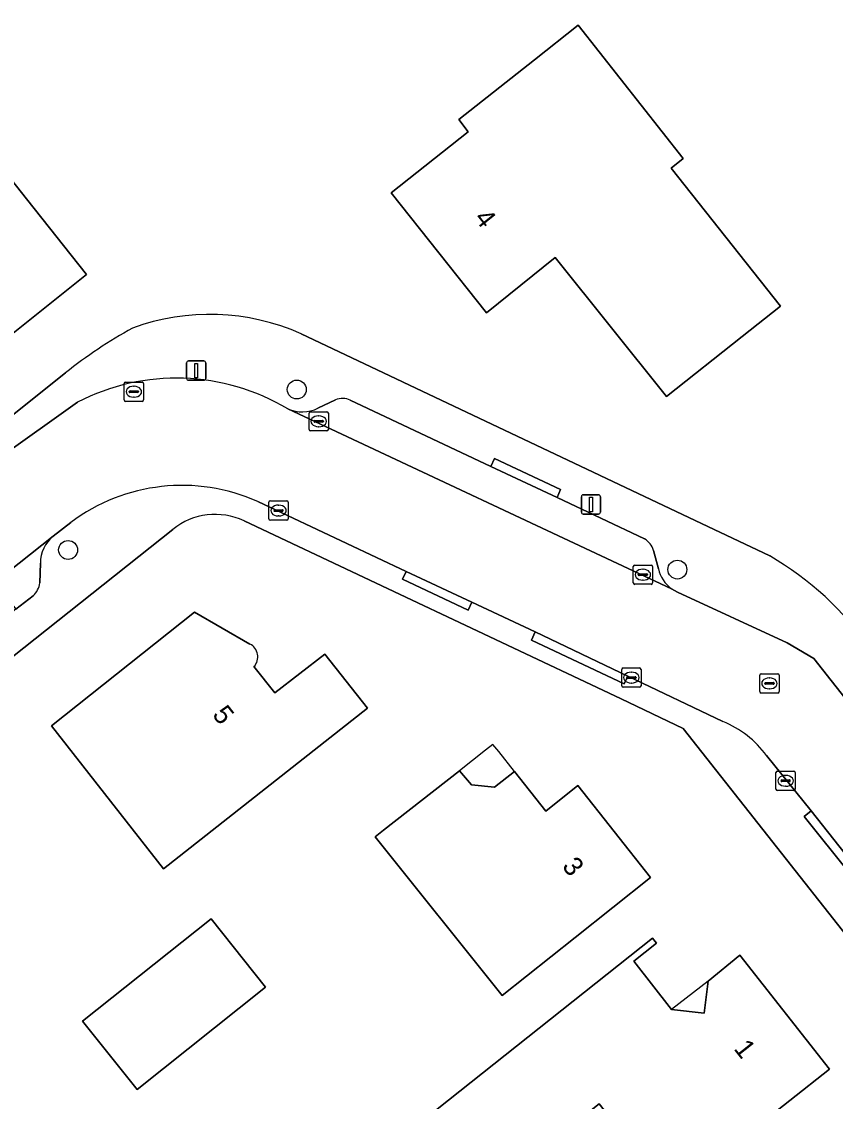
# Model space of a CAD drawing. Extents: x 159626 to 160723, y 388173 to 389416.
# Drawn here: x 159947.2 to 159989.4, y 388604.8 to 388660.7 of the extents above; entities that cross this region are included whole.
import ezdxf

# ---------------------------------------------------------------- set-up
doc = ezdxf.new("R2010")
doc.units = 0
for name, color, linetype in [('IMGEO_Boom', 7, 'Continuous'), ('IMGEO_Erf', 7, 'Continuous'), ('IMGEO_Kolk', 7, 'Continuous'), ('IMGEO_Lichtmast', 7, 'Continuous'), ('IMGEO_Pand', 7, 'Continuous'), ('IMGEO_Pand_nummerreeks', 7, 'Continuous'), ('IMGEO_Pand_overbouw', 7, 'Continuous'), ('IMGEO_Parkeervlak_open', 7, 'Continuous'), ('IMGEO_Rijbaan_lokaal_open', 7, 'Continuous'), ('IMGEO_Rioolput', 7, 'Continuous'), ('IMGEO_Voetpad_open', 7, 'Continuous')]:
    doc.layers.add(name, color=color, linetype=linetype)

msp = doc.modelspace()

# ---------------------------------------------------------------- linework, layer by layer
at = {"layer": 'IMGEO_Boom'}
for centre in [(159961.483, 388641.658), (159949.629, 388633.346), (159981.213, 388632.329)]:
    msp.add_circle(centre, 0.489, dxfattribs=at)
at = {"layer": 'IMGEO_Erf'}
for points in [[(159944.685, 388642.929), (159944.5, 388641.838), (159942.579, 388640.32), (159941.469, 388640.402), (159941.101, 388640.109), (159936.4, 388646.038), (159938.761, 388647.945), (159939.373, 388648.442), (159938.292, 388649.91), (159937.645, 388649.313), (159933.084, 388655.085), (159937.002, 388658.193), (159940.192, 388660.724), (159947.475, 388651.543), (159950.583, 388647.626)], [(159981.523, 388653.629), (159980.897, 388653.134), (159986.558, 388645.973), (159984.577, 388644.407), (159980.655, 388641.305), (159974.884, 388648.501), (159971.32, 388645.631), (159966.37, 388651.85), (159970.377, 388655.018), (159969.882, 388655.644), (159973.805, 388658.745), (159976.066, 388660.532)], [(159965.554, 388618.482), (159965.985, 388618.82), (159969.918, 388621.906), (159970.55, 388621.181), (159971.742, 388621.064), (159972.765, 388621.862), (159974.401, 388619.82), (159976.062, 388621.142), (159979.827, 388616.37), (159975.909, 388613.265), (159972.123, 388610.264)], [(159950.38, 388608.93), (159957.042, 388614.232), (159959.861, 388610.685), (159953.201, 388605.385)], [(159977.152, 388604.649), (159974.803, 388602.785), (159974.431, 388603.254), (159971.308, 388600.776), (159969.731, 388599.525), (159966.996, 388602.972), (159971.696, 388606.701), (159979.927, 388613.231), (159980.13, 388612.965), (159978.952, 388612.041), (159980.918, 388609.537), (159982.606, 388609.353), (159982.809, 388611.002), (159984.451, 388612.35), (159989.108, 388606.451), (159980.88, 388599.95)]]:
    msp.add_lwpolyline(points, close=True, dxfattribs=at)
for points in [[(159961.709, 388644.549), (159982.465, 388634.72), (159986.01, 388633.035)], [(159939.758, 388634.891), (159940.172, 388635.094), (159949.489, 388642.527)], [(159994.869, 388607.162), (159981.506, 388624.102), (159978.304, 388625.626), (159958.752, 388634.855)], [(159955.063, 388634.415), (159911.466, 388599.82)], [(159948.766, 388624.226), (159956.185, 388630.121), (159959.052, 388628.472)], [(159959.266, 388627.3), (159960.348, 388625.938), (159962.942, 388627.943), (159965.142, 388625.158), (159954.57, 388616.83), (159948.766, 388624.226)]]:
    msp.add_lwpolyline(points, dxfattribs=at)
for centre, radius, start, end in [((159956.977, 388633.896), 11.656, 66.0505, 110.1089), ((159965.53, 388622.181), 25.909, 118.9981, 128.2528), ((159957.259, 388631.684), 3.505, 64.7934, 128.8101), ((159977.913, 388619.061), 16.15, 34.6568, 59.9116), ((159958.727, 388627.807), 0.74, 316.7507, 63.945)]:
    msp.add_arc(centre, radius, start, end, dxfattribs=at)
at = {"layer": 'IMGEO_Kolk'}
for p, q in [((159962.194, 388640.512), (159963.046, 388640.512)), ((159962.119, 388639.586), (159962.119, 388640.438)), ((159962.378, 388640.006), (159962.378, 388640.018)), ((159962.816, 388639.969), (159962.418, 388639.969)), ((159962.421, 388640.055), (159962.819, 388640.055)), ((159962.607, 388640.292), (159962.632, 388640.292)), ((159962.862, 388640.018), (159962.862, 388640.006)), ((159963.12, 388640.438), (159963.12, 388639.586)), ((159963.046, 388639.512), (159962.194, 388639.512)), ((159962.63, 388639.732), (159962.605, 388639.732)), ((159960.038, 388634.963), (159960.038, 388635.815)), ((159960.113, 388635.889), (159960.965, 388635.889)), ((159960.34, 388635.432), (159960.738, 388635.432)), ((159960.526, 388635.669), (159960.551, 388635.669)), ((159961.039, 388635.815), (159961.039, 388634.963)), ((159960.965, 388634.889), (159960.113, 388634.889)), ((159960.297, 388635.383), (159960.297, 388635.395)), ((159960.735, 388635.346), (159960.337, 388635.346)), ((159960.549, 388635.109), (159960.524, 388635.109)), ((159960.781, 388635.395), (159960.781, 388635.383)), ((159978.927, 388631.64), (159978.927, 388632.492)), ((159979.002, 388632.566), (159979.854, 388632.566)), ((159979.186, 388632.06), (159979.186, 388632.072)), ((159979.229, 388632.109), (159979.627, 388632.109)), ((159979.415, 388632.346), (159979.44, 388632.346)), ((159979.67, 388632.072), (159979.67, 388632.06)), ((159979.928, 388632.492), (159979.928, 388631.64)), ((159979.854, 388631.566), (159979.002, 388631.566)), ((159979.624, 388632.023), (159979.226, 388632.023)), ((159979.438, 388631.786), (159979.413, 388631.786)), ((159978.329, 388626.307), (159978.329, 388627.159)), ((159978.404, 388627.233), (159979.256, 388627.233)), ((159979.33, 388627.159), (159979.33, 388626.307)), ((159978.588, 388626.727), (159978.588, 388626.739)), ((159979.026, 388626.69), (159978.628, 388626.69)), ((159978.631, 388626.776), (159979.029, 388626.776)), ((159978.817, 388627.013), (159978.842, 388627.013)), ((159979.072, 388626.739), (159979.072, 388626.727)), ((159979.256, 388626.233), (159978.404, 388626.233)), ((159978.84, 388626.453), (159978.815, 388626.453)), ((159986.326, 388620.96), (159986.326, 388621.812)), ((159986.401, 388621.886), (159987.253, 388621.886)), ((159986.628, 388621.429), (159987.026, 388621.429)), ((159986.814, 388621.666), (159986.839, 388621.666)), ((159987.327, 388621.812), (159987.327, 388620.96)), ((159987.253, 388620.886), (159986.401, 388620.886)), ((159986.585, 388621.38), (159986.585, 388621.392)), ((159987.023, 388621.343), (159986.625, 388621.343)), ((159986.837, 388621.106), (159986.812, 388621.106)), ((159987.069, 388621.392), (159987.069, 388621.38))]:
    msp.add_line(p, q, dxfattribs=at)
for points in [[(159962.194, 388640.512), (159963.046, 388640.512)], [(159962.119, 388639.586), (159962.119, 388640.438)], [(159963.12, 388640.438), (159963.12, 388639.586)], [(159963.046, 388639.512), (159962.194, 388639.512)], [(159960.038, 388634.963), (159960.038, 388635.815)], [(159960.113, 388635.889), (159960.965, 388635.889)], [(159961.039, 388635.815), (159961.039, 388634.963)], [(159960.965, 388634.889), (159960.113, 388634.889)], [(159978.927, 388631.64), (159978.927, 388632.492)], [(159979.002, 388632.566), (159979.854, 388632.566)], [(159979.928, 388632.492), (159979.928, 388631.64)], [(159979.854, 388631.566), (159979.002, 388631.566)], [(159978.329, 388626.307), (159978.329, 388627.159)], [(159978.404, 388627.233), (159979.256, 388627.233)], [(159979.33, 388627.159), (159979.33, 388626.307)], [(159979.256, 388626.233), (159978.404, 388626.233)], [(159986.326, 388620.96), (159986.326, 388621.812)], [(159986.401, 388621.886), (159987.253, 388621.886)], [(159987.327, 388621.812), (159987.327, 388620.96)], [(159987.253, 388620.886), (159986.401, 388620.886)]]:
    msp.add_lwpolyline(points, dxfattribs=at)
for centre, radius, start, end in [((159962.196, 388640.436), 0.0765, 91.552, 178.448), ((159962.196, 388640.436), 0.0765, 91.552, 178.448), ((159963.044, 388640.436), 0.0765, 1.552, 88.448), ((159963.044, 388640.436), 0.0765, 1.552, 88.448), ((159962.418, 388640.015), 0.0403, 85.8775, 175.7526), ((159962.415, 388640.005), 0.0366, 178.938, 274.7102), ((159962.819, 388640.012), 0.043, 264.8664, 352.4533), ((159962.823, 388640.017), 0.0386, 1.7309, 96.639), ((159962.196, 388639.588), 0.0765, 181.552, 268.448), ((159962.196, 388639.588), 0.0765, 181.552, 268.448), ((159963.044, 388639.588), 0.0765, 271.552, 358.448), ((159963.044, 388639.588), 0.0765, 271.552, 358.448), ((159960.115, 388635.813), 0.0765, 91.552, 178.448), ((159960.115, 388635.813), 0.0765, 91.552, 178.448), ((159960.337, 388635.392), 0.0403, 85.8775, 175.7526), ((159960.742, 388635.394), 0.0386, 1.7309, 96.639), ((159960.963, 388635.813), 0.0765, 1.552, 88.448), ((159960.963, 388635.813), 0.0765, 1.552, 88.448), ((159960.115, 388634.965), 0.0765, 181.552, 268.448), ((159960.115, 388634.965), 0.0765, 181.552, 268.448), ((159960.334, 388635.382), 0.0366, 178.938, 274.7102), ((159960.738, 388635.389), 0.043, 264.8664, 352.4533), ((159960.963, 388634.965), 0.0765, 271.552, 358.448), ((159960.963, 388634.965), 0.0765, 271.552, 358.448), ((159979.004, 388632.49), 0.0765, 91.552, 178.448), ((159979.004, 388632.49), 0.0765, 91.552, 178.448), ((159979.226, 388632.069), 0.0403, 85.8775, 175.7526), ((159979.223, 388632.059), 0.0366, 178.938, 274.7102), ((159979.627, 388632.066), 0.043, 264.8664, 352.4533), ((159979.631, 388632.071), 0.0386, 1.7309, 96.639), ((159979.852, 388632.49), 0.0765, 1.552, 88.448), ((159979.852, 388632.49), 0.0765, 1.552, 88.448), ((159979.004, 388631.642), 0.0765, 181.552, 268.448), ((159979.004, 388631.642), 0.0765, 181.552, 268.448), ((159979.852, 388631.642), 0.0765, 271.552, 358.448), ((159979.852, 388631.642), 0.0765, 271.552, 358.448), ((159978.406, 388627.157), 0.0765, 91.552, 178.448), ((159978.406, 388627.157), 0.0765, 91.552, 178.448), ((159979.254, 388627.157), 0.0765, 1.552, 88.448), ((159979.254, 388627.157), 0.0765, 1.552, 88.448), ((159978.628, 388626.736), 0.0403, 85.8775, 175.7526), ((159978.625, 388626.726), 0.0366, 178.938, 274.7102), ((159979.029, 388626.733), 0.043, 264.8664, 352.4533), ((159979.033, 388626.738), 0.0386, 1.7309, 96.639), ((159978.406, 388626.309), 0.0765, 181.552, 268.448), ((159978.406, 388626.309), 0.0765, 181.552, 268.448), ((159979.254, 388626.309), 0.0765, 271.552, 358.448), ((159979.254, 388626.309), 0.0765, 271.552, 358.448), ((159986.403, 388621.81), 0.0765, 91.552, 178.448), ((159986.403, 388621.81), 0.0765, 91.552, 178.448), ((159986.625, 388621.389), 0.0403, 85.8775, 175.7526), ((159987.03, 388621.391), 0.0386, 1.7309, 96.639), ((159987.251, 388621.81), 0.0765, 1.552, 88.448), ((159987.251, 388621.81), 0.0765, 1.552, 88.448), ((159986.403, 388620.962), 0.0765, 181.552, 268.448), ((159986.403, 388620.962), 0.0765, 181.552, 268.448), ((159986.622, 388621.379), 0.0366, 178.938, 274.7102), ((159987.026, 388621.386), 0.043, 264.8664, 352.4533), ((159987.251, 388620.962), 0.0765, 271.552, 358.448), ((159987.251, 388620.962), 0.0765, 271.552, 358.448)]:
    msp.add_arc(centre, radius, start, end, dxfattribs=at)
for centre, major_axis, ratio, start_param, end_param in [((159962.606, 388640.012), (-0.387, 0.002), 0.722429, 4.712389, 7.853982), ((159962.631, 388640.012), (-0.39, 0.002), 0.717154, 1.570796, 4.712389), ((159960.525, 388635.389), (-0.387, 0.002), 0.722429, 4.712389, 7.853982), ((159960.55, 388635.389), (-0.39, 0.002), 0.717154, 1.570796, 4.712389), ((159979.414, 388632.066), (-0.387, 0.002), 0.722429, 4.712389, 7.853982), ((159979.439, 388632.066), (-0.39, 0.002), 0.717154, 1.570796, 4.712389), ((159978.816, 388626.733), (-0.387, 0.002), 0.722429, 4.712389, 7.853982), ((159978.841, 388626.733), (-0.39, 0.002), 0.717154, 1.570796, 4.712389), ((159986.813, 388621.386), (-0.387, 0.002), 0.722429, 4.712389, 7.853982), ((159986.838, 388621.386), (-0.39, 0.002), 0.717154, 1.570796, 4.712389)]:
    msp.add_ellipse(centre, major_axis=major_axis, ratio=ratio, start_param=start_param, end_param=end_param, dxfattribs=at)
at = {"layer": 'IMGEO_Lichtmast'}
for p, q in [((159955.774, 388642.238), (159955.774, 388643.038)), ((159955.774, 388643.038), (159955.774, 388642.238)), ((159955.874, 388643.138), (159956.664, 388643.138)), ((159956.664, 388643.138), (159955.874, 388643.138)), ((159956.764, 388643.038), (159956.764, 388642.238)), ((159956.764, 388642.238), (159956.764, 388643.038)), ((159956.664, 388642.138), (159955.874, 388642.138)), ((159955.874, 388642.138), (159956.664, 388642.138)), ((159976.236, 388635.305), (159976.236, 388636.105)), ((159976.236, 388636.105), (159976.236, 388635.305)), ((159976.336, 388636.205), (159977.126, 388636.205)), ((159977.126, 388636.205), (159976.336, 388636.205)), ((159977.226, 388636.105), (159977.226, 388635.305)), ((159977.226, 388635.305), (159977.226, 388636.105)), ((159977.126, 388635.205), (159976.336, 388635.205)), ((159976.336, 388635.205), (159977.126, 388635.205))]:
    msp.add_line(p, q, dxfattribs=at)
for points in [[(159956.194, 388643.013), (159956.344, 388643.013), (159956.344, 388642.263), (159956.194, 388642.263), (159956.194, 388643.013)], [(159976.656, 388636.08), (159976.806, 388636.08), (159976.806, 388635.33), (159976.656, 388635.33), (159976.656, 388636.08)]]:
    msp.add_lwpolyline(points, dxfattribs=at)
for centre, start, end in [((159955.874, 388643.038), 90, 180), ((159955.874, 388643.038), 90, 180), ((159956.664, 388643.038), 0, 90), ((159956.664, 388643.038), 360, 90), ((159955.874, 388642.238), 180, 270), ((159955.874, 388642.238), 180, 270), ((159956.664, 388642.238), 270, 0), ((159956.664, 388642.238), 270, 0), ((159976.336, 388636.105), 90, 180), ((159976.336, 388636.105), 90, 180), ((159977.126, 388636.105), 0, 90), ((159977.126, 388636.105), 360, 90), ((159976.336, 388635.305), 180, 270), ((159976.336, 388635.305), 180, 270), ((159977.126, 388635.305), 270, 0), ((159977.126, 388635.305), 270, 0)]:
    msp.add_arc(centre, 0.1, start, end, dxfattribs=at)
at = {"layer": 'IMGEO_Pand'}
for points in [[(159937.645, 388649.313), (159938.292, 388649.91), (159939.373, 388648.442), (159938.761, 388647.945), (159936.4, 388646.038), (159941.101, 388640.109), (159941.469, 388640.402), (159942.579, 388640.32), (159944.5, 388641.838), (159944.685, 388642.929), (159950.583, 388647.626), (159947.475, 388651.543), (159940.192, 388660.724), (159937.002, 388658.193), (159933.084, 388655.085)], [(159984.577, 388644.407), (159986.558, 388645.973), (159980.897, 388653.134), (159981.523, 388653.629), (159976.066, 388660.532), (159973.805, 388658.745), (159969.882, 388655.644), (159970.377, 388655.018), (159966.37, 388651.85), (159971.32, 388645.631), (159974.884, 388648.501), (159980.655, 388641.305)], [(159969.918, 388621.906), (159965.985, 388618.82), (159965.554, 388618.482), (159972.123, 388610.264), (159975.909, 388613.265), (159979.827, 388616.37), (159976.062, 388621.142), (159974.401, 388619.82), (159972.765, 388621.862), (159971.742, 388621.064), (159970.55, 388621.181)], [(159953.201, 388605.385), (159959.861, 388610.685), (159957.042, 388614.232), (159950.38, 388608.93)], [(159989.108, 388606.451), (159984.451, 388612.35), (159982.809, 388611.002), (159982.606, 388609.353), (159980.918, 388609.537), (159978.952, 388612.041), (159980.13, 388612.965), (159979.927, 388613.231), (159971.696, 388606.701), (159966.996, 388602.972), (159969.731, 388599.525), (159971.308, 388600.776), (159974.431, 388603.254), (159974.803, 388602.785), (159977.152, 388604.649), (159980.88, 388599.95)]]:
    msp.add_lwpolyline(points, close=True, dxfattribs=at)
msp.add_lwpolyline([(159959.052, 388628.472), (159956.185, 388630.121), (159948.766, 388624.226), (159954.57, 388616.83), (159965.142, 388625.158), (159962.942, 388627.943), (159960.348, 388625.938), (159959.266, 388627.3)], dxfattribs=at)
msp.add_arc((159958.727, 388627.807), 0.74, 316.7507, 63.945, dxfattribs=at)
at = {"layer": 'IMGEO_Pand_overbouw'}
for points in [[(159969.918, 388621.906), (159970.55, 388621.181), (159971.742, 388621.064), (159972.765, 388621.862), (159971.959, 388622.898), (159971.655, 388623.275), (159971.271, 388622.975)], [(159982.809, 388611.002), (159980.918, 388609.537), (159982.606, 388609.353)]]:
    msp.add_lwpolyline(points, close=True, dxfattribs=at)
at = {"layer": 'IMGEO_Parkeervlak_open'}
for points in [[(159963.493, 388641.127), (159962.582, 388640.687)], [(159979.509, 388633.923), (159974.977, 388636.06), (159971.546, 388637.677), (159964.258, 388641.113)], [(159961.021, 388640.652), (159980.906, 388631.34)], [(159948.847, 388634.062), (159946.507, 388632.202), (159945.827, 388631.669), (159946.926, 388630.28), (159947.812, 388630.975)], [(159980.232, 388632.374), (159979.983, 388633.323)], [(159948.164, 388631.645), (159948.193, 388632.661)]]:
    msp.add_lwpolyline(points, dxfattribs=at)
for centre, radius, start, end in [((159963.859, 388640.246), 0.955, 65.3251, 112.578), ((159961.763, 388642.371), 1.872, 246.6401, 295.9288), ((159950.025, 388632.659), 1.832, 130.0141, 179.9387), ((159978.969, 388633.009), 1.062, 17.2048, 59.4127), ((159981.946, 388632.754), 1.755, 192.5149, 233.6807), ((159947.098, 388631.777), 1.074, 311.6505, 352.9171)]:
    msp.add_arc(centre, radius, start, end, dxfattribs=at)
at = {"layer": 'IMGEO_Rijbaan_lokaal_open'}
for points in [[(159950.122, 388641.005), (159946.049, 388638.119), (159943.49, 388636.12), (159942.807, 388635.575), (159945.827, 388631.669), (159946.507, 388632.202), (159948.847, 388634.062), (159949.767, 388634.774)], [(159985.833, 388622.694), (159988.152, 388619.823), (159990.497, 388616.852), (159994.461, 388611.83), (159998.383, 388614.922), (159988.285, 388627.721), (159986.905, 388628.53), (159981.225, 388631.153), (159980.906, 388631.34), (159961.021, 388640.652)], [(159959.462, 388635.859), (159967.155, 388632.23), (159970.561, 388630.635), (159973.844, 388629.101), (159978.653, 388626.808), (159983.578, 388624.453)]]:
    msp.add_lwpolyline(points, dxfattribs=at)
for centre, radius, start, end in [((159955.255, 388631.046), 11.204, 59.0237, 117.2662), ((159955.54, 388627.05), 9.642, 65.997, 126.7742), ((159981.682, 388619.697), 5.12, 35.8263, 68.2621)]:
    msp.add_arc(centre, radius, start, end, dxfattribs=at)
at = {"layer": 'IMGEO_Rioolput'}
for p, q in [((159952.537, 388641.122), (159952.537, 388641.974)), ((159952.612, 388642.048), (159953.464, 388642.048)), ((159952.839, 388641.591), (159953.237, 388641.591)), ((159953.025, 388641.828), (159953.05, 388641.828)), ((159953.538, 388641.974), (159953.538, 388641.122)), ((159953.464, 388641.048), (159952.612, 388641.048)), ((159952.796, 388641.542), (159952.796, 388641.554)), ((159953.234, 388641.505), (159952.836, 388641.505)), ((159953.048, 388641.268), (159953.023, 388641.268)), ((159953.28, 388641.554), (159953.28, 388641.542)), ((159985.487, 388626.008), (159985.487, 388626.86)), ((159985.562, 388626.934), (159986.414, 388626.934)), ((159985.789, 388626.477), (159986.187, 388626.477)), ((159985.975, 388626.714), (159986, 388626.714)), ((159986.488, 388626.86), (159986.488, 388626.008)), ((159986.414, 388625.934), (159985.562, 388625.934)), ((159985.746, 388626.428), (159985.746, 388626.44)), ((159986.184, 388626.391), (159985.786, 388626.391)), ((159985.998, 388626.154), (159985.973, 388626.154)), ((159986.23, 388626.44), (159986.23, 388626.428))]:
    msp.add_line(p, q, dxfattribs=at)
for points in [[(159952.537, 388641.122), (159952.537, 388641.974)], [(159952.612, 388642.048), (159953.464, 388642.048)], [(159953.538, 388641.974), (159953.538, 388641.122)], [(159953.464, 388641.048), (159952.612, 388641.048)], [(159985.487, 388626.008), (159985.487, 388626.86)], [(159985.562, 388626.934), (159986.414, 388626.934)], [(159986.488, 388626.86), (159986.488, 388626.008)], [(159986.414, 388625.934), (159985.562, 388625.934)]]:
    msp.add_lwpolyline(points, dxfattribs=at)
for centre, radius, start, end in [((159952.614, 388641.972), 0.0765, 91.552, 178.448), ((159952.614, 388641.972), 0.0765, 91.552, 178.448), ((159952.836, 388641.551), 0.0403, 85.8775, 175.7526), ((159953.241, 388641.553), 0.0386, 1.7309, 96.639), ((159953.462, 388641.972), 0.0765, 1.552, 88.448), ((159953.462, 388641.972), 0.0765, 1.552, 88.448), ((159952.614, 388641.124), 0.0765, 181.552, 268.448), ((159952.614, 388641.124), 0.0765, 181.552, 268.448), ((159952.833, 388641.541), 0.0366, 178.938, 274.7102), ((159953.237, 388641.548), 0.043, 264.8664, 352.4533), ((159953.462, 388641.124), 0.0765, 271.552, 358.448), ((159953.462, 388641.124), 0.0765, 271.552, 358.448), ((159985.564, 388626.858), 0.0765, 91.552, 178.448), ((159985.564, 388626.858), 0.0765, 91.552, 178.448), ((159985.786, 388626.437), 0.0403, 85.8775, 175.7526), ((159986.191, 388626.439), 0.0386, 1.7309, 96.639), ((159986.412, 388626.858), 0.0765, 1.552, 88.448), ((159986.412, 388626.858), 0.0765, 1.552, 88.448), ((159985.564, 388626.01), 0.0765, 181.552, 268.448), ((159985.564, 388626.01), 0.0765, 181.552, 268.448), ((159985.783, 388626.427), 0.0366, 178.938, 274.7102), ((159986.187, 388626.434), 0.043, 264.8664, 352.4533), ((159986.412, 388626.01), 0.0765, 271.552, 358.448), ((159986.412, 388626.01), 0.0765, 271.552, 358.448)]:
    msp.add_arc(centre, radius, start, end, dxfattribs=at)
for centre, major_axis, ratio, start_param, end_param in [((159953.024, 388641.548), (-0.387, 0.002), 0.722429, 4.712389, 7.853982), ((159953.049, 388641.548), (-0.39, 0.002), 0.717154, 1.570796, 4.712389), ((159985.974, 388626.434), (-0.387, 0.002), 0.722429, 4.712389, 7.853982), ((159985.999, 388626.434), (-0.39, 0.002), 0.717154, 1.570796, 4.712389)]:
    msp.add_ellipse(centre, major_axis=major_axis, ratio=ratio, start_param=start_param, end_param=end_param, dxfattribs=at)
at = {"layer": 'IMGEO_Voetpad_open'}
for points in [[(159986.01, 388633.035), (159982.465, 388634.72), (159961.709, 388644.549)], [(159949.489, 388642.527), (159940.172, 388635.094), (159937.609, 388633.116)], [(159962.582, 388640.687), (159963.493, 388641.127)], [(159964.258, 388641.113), (159971.546, 388637.677), (159971.739, 388638.078), (159975.157, 388636.481), (159974.977, 388636.06), (159979.509, 388633.923)], [(159940.194, 388633.536), (159942.807, 388635.575), (159943.49, 388636.12), (159946.049, 388638.119), (159950.122, 388641.005)], [(159983.578, 388624.453), (159978.653, 388626.808), (159978.45, 388626.414), (159973.656, 388628.679), (159973.844, 388629.101), (159970.561, 388630.635), (159970.367, 388630.223), (159966.964, 388631.825), (159967.155, 388632.23), (159959.462, 388635.859)], [(159958.752, 388634.855), (159978.304, 388625.626), (159981.506, 388624.102), (159994.869, 388607.162), (159996.498, 388609.249), (159996.163, 388609.674), (159994.461, 388611.83), (159990.497, 388616.852), (159990.147, 388616.581), (159987.791, 388619.541), (159988.152, 388619.823), (159985.833, 388622.694)], [(159911.466, 388599.82), (159955.063, 388634.415)], [(159949.767, 388634.774), (159948.847, 388634.062)], [(159979.983, 388633.323), (159980.232, 388632.374)], [(159948.193, 388632.661), (159948.164, 388631.645)], [(159947.812, 388630.975), (159946.926, 388630.28), (159935.008, 388620.788), (159935.318, 388620.396), (159929.383, 388615.697), (159929.073, 388616.089), (159917.343, 388606.776)], [(159980.906, 388631.34), (159981.225, 388631.153), (159986.905, 388628.53), (159988.285, 388627.721), (159998.383, 388614.922), (160000.014, 388612.793), (160000.751, 388611.921), (160002.97, 388613.298), (160000, 388617.069)]]:
    msp.add_lwpolyline(points, dxfattribs=at)
for points in [[(159971.546, 388637.677), (159974.977, 388636.06), (159975.157, 388636.481), (159971.739, 388638.078)], [(159967.155, 388632.23), (159966.964, 388631.825), (159970.367, 388630.223), (159970.561, 388630.635)], [(159978.653, 388626.808), (159973.844, 388629.101), (159973.656, 388628.679), (159978.45, 388626.414)], [(159988.152, 388619.823), (159987.791, 388619.541), (159990.147, 388616.581), (159990.497, 388616.852)]]:
    msp.add_lwpolyline(points, close=True, dxfattribs=at)
for centre, radius, start, end in [((159956.977, 388633.896), 11.656, 66.0505, 110.1089), ((159965.53, 388622.181), 25.909, 118.9981, 128.2528), ((159955.255, 388631.046), 11.204, 59.0237, 117.2662), ((159963.859, 388640.246), 0.955, 65.3251, 112.578), ((159961.763, 388642.371), 1.872, 246.6401, 295.9288), ((159955.54, 388627.05), 9.642, 65.997, 126.7742), ((159957.259, 388631.684), 3.505, 64.7934, 128.8101), ((159950.025, 388632.659), 1.832, 130.0141, 179.9387), ((159978.969, 388633.009), 1.062, 17.2048, 59.4127), ((159977.913, 388619.061), 16.15, 34.6568, 59.9116), ((159981.946, 388632.754), 1.755, 192.5149, 233.6807), ((159947.098, 388631.777), 1.074, 311.6505, 352.9171), ((159981.682, 388619.697), 5.12, 35.8263, 68.2621)]:
    msp.add_arc(centre, radius, start, end, dxfattribs=at)

# ---------------------------------------------------------------- texts
at = {"layer": 'IMGEO_Pand_nummerreeks'}
for s, rotation, p in [('4', 308.518, (159970.645, 388650.526)), ('5', 308.4643, (159957.067, 388624.794)), ('3', 308.2726, (159975.199, 388616.941)), ('1', 308.2906, (159984.105, 388607.495))]:
    msp.add_text(s, height=1, rotation=rotation, dxfattribs=at).set_placement(p)

doc.saveas('drawing.dxf')
